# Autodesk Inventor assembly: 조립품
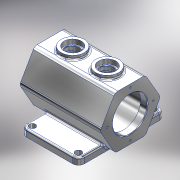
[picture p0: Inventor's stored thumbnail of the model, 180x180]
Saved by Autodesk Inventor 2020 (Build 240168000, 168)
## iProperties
Created: 2021-06
Part Number: 조립품
Document SubType Name: Assembly
Designer: 605-3
Author: 605-3
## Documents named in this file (2)
- C:\Users\605-3\Desktop\710606V1015\조립품.iam
- C:\Users\605-3\Desktop\710606V1015\본체.ipt
